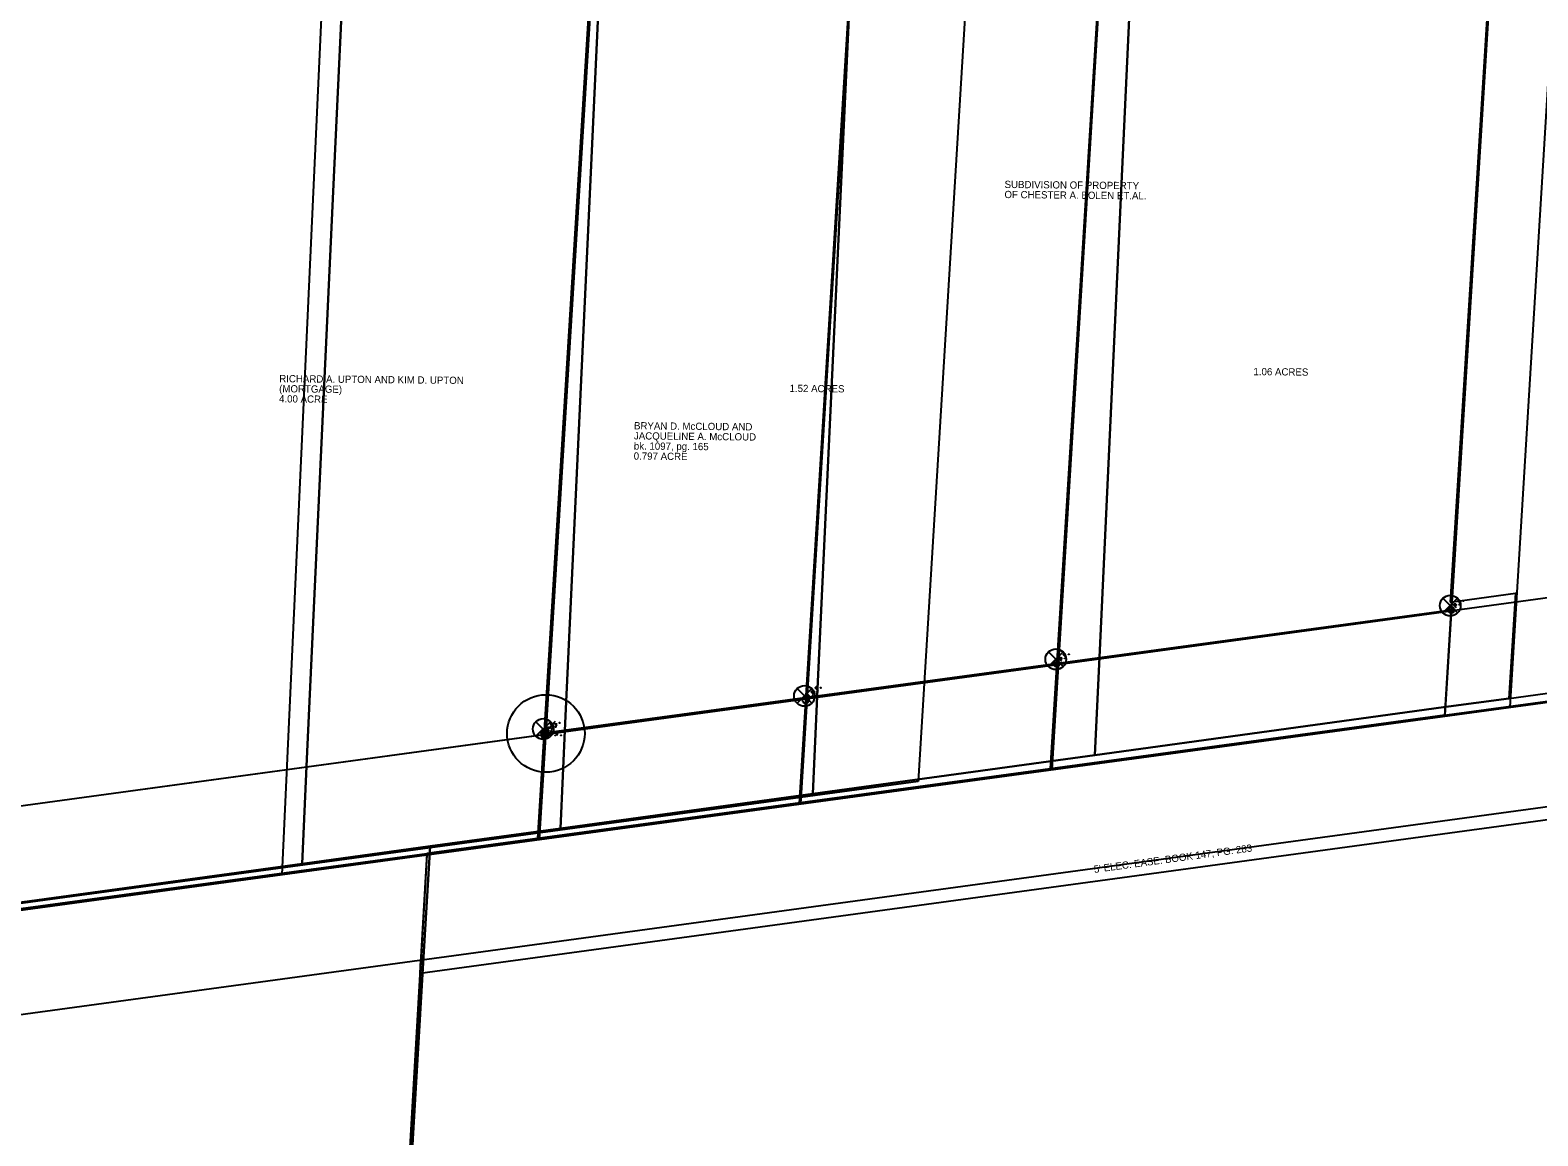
# Model space of a CAD drawing. Extents: x 1532954 to 1577849, y 698998 to 706606.
# Drawn here: x 1572810 to 1573393, y 702918 to 703345 of the extents above; entities that cross this region are included whole.
import ezdxf

# ---------------------------------------------------------------- set-up
doc = ezdxf.new("R2010")
doc.units = 0
for name, color, linetype in [('Default', 7, 'Continuous'), ('DV_X_Lot_Line', 7, 'Continuous'), ('DV_X_Property_Line', 7, 'Continuous'), ('RW_X_CL', 7, 'Continuous'), ('RW_X_Esmt_SH', 7, 'Continuous'), ('RW_X_Esmt_U', 7, 'Continuous'), ('RW_X_Fee_RW', 7, 'Continuous'), ('RW_X_Text', 7, 'Continuous'), ('SC_Scratch1', 7, 'Continuous'), ('SC_Scratch10', 7, 'Continuous'), ('SC_Scratch2', 7, 'Continuous'), ('SC_Scratch3', 7, 'Continuous'), ('SC_Scratch4', 7, 'Continuous'), ('SC_Scratch9', 7, 'Continuous'), ('SV_X_Mon_Cells_Found', 7, 'Continuous')]:
    doc.layers.add(name, color=color, linetype=linetype)

msp = doc.modelspace()

# ---------------------------------------------------------------- linework, layer by layer
at = {"layer": 'Default'}
for p, q in [((1573356.22, 703125.76), (1573361.88, 703120.1)), ((1573356.22, 703120.1), (1573361.88, 703125.76)), ((1573359.05, 703122.93), (1573359.05, 703122.93)), ((1573203.7, 703105.01), (1573209.36, 703099.35)), ((1573203.7, 703099.35), (1573209.36, 703105.01)), ((1573206.53, 703102.18), (1573206.53, 703102.18)), ((1573106.52, 703090.83), (1573112.18, 703085.17)), ((1573106.52, 703085.17), (1573112.18, 703090.83)), ((1573109.35, 703088), (1573109.35, 703088)), ((1573005.53, 703078.04), (1573011.18, 703072.39)), ((1573005.53, 703072.39), (1573011.18, 703078.04)), ((1573008.35, 703075.22), (1573008.35, 703075.22))]:
    msp.add_line(p, q, dxfattribs=at)
for centre in [(1573359.05, 703122.93), (1573206.53, 703102.18), (1573109.35, 703088), (1573008.35, 703075.22)]:
    msp.add_circle(centre, 4, dxfattribs=at)
at = {"layer": 'DV_X_Lot_Line'}
msp.add_line((1572963.4, 703026.58), (1572823.01, 700550.44), dxfattribs=at)
at = {"layer": 'DV_X_Property_Line'}
for p, q in [((1572907.39, 703018.94), (1572924.6, 703393.96)), ((1573006.97, 703032.51), (1573028.82, 703388.75)), ((1573108.02, 703046.29), (1573128.72, 703383.76)), ((1573205.13, 703059.52), (1573224.73, 703378.97))]:
    msp.add_line(p, q, dxfattribs=at)
at = {"layer": 'RW_X_CL'}
msp.add_line((1573382.25, 703083.67), (1573411.32, 703561.68), dxfattribs=at)
at = {"layer": 'RW_X_Esmt_SH'}
for p, q in [((1571959, 702849.32), (1574870.56, 703246.15)), ((1571963.78, 702930.71), (1573359.47, 703120.93))]:
    msp.add_line(p, q, dxfattribs=at)
at = {"layer": 'RW_X_Esmt_U'}
for q in [(1573728.73, 703085.47), (1572961.09, 702985.9)]:
    msp.add_line((1572960.8, 702980.81), q, dxfattribs=at)
at = {"layer": 'RW_X_Fee_RW'}
msp.add_line((1573356.99, 703080.22), (1573386.06, 703558.24), dxfattribs=at)
at = {"layer": 'SC_Scratch1'}
for points in [[(1572932.18, 703390.15), (1572927.2, 703283.07), (1572917, 703063.72), (1572915.11, 703023.08), (1572800.34, 703007.35), (1572687.31, 702991.85), (1572689.2, 703032.48), (1572701.55, 703298.03), (1572706.35, 703401.33), (1572818.4, 703395.78)], [(1573031.18, 703385.25), (1573026.13, 703276.51), (1573016.87, 703077.41), (1573014.98, 703036.77), (1572964.59, 703029.87), (1572915.11, 703023.08), (1572917, 703063.72), (1572927.2, 703283.07), (1572932.18, 703390.15)], [(1573127.9, 703380.47), (1573122.77, 703270.11), (1573114.43, 703090.78), (1573112.54, 703050.15), (1573014.98, 703036.77), (1573016.87, 703077.41), (1573026.13, 703276.51), (1573031.18, 703385.25)], [(1573174.57, 703378.16), (1573225.57, 703375.64), (1573236.04, 703375.12), (1573223.52, 703105.74), (1573221.63, 703065.11), (1573207.45, 703063.17), (1573112.54, 703050.15), (1573114.43, 703090.78), (1573122.77, 703270.11), (1573127.9, 703380.47)], [(1573359.05, 703124.32), (1573384.32, 703127.79), (1573381.77, 703087.06), (1573356.5, 703083.6), (1573221.63, 703065.11), (1573223.52, 703105.74), (1573236.04, 703375.12), (1573374.34, 703368.27)]]:
    msp.add_lwpolyline(points, close=True, dxfattribs=at)
for points in [[(1572818.71, 700543.9), (1572962.2, 702989.16), (1572964.59, 703029.87), (1573014.98, 703036.77), (1573112.54, 703050.15), (1573207.45, 703063.17), (1573221.63, 703065.11), (1573356.5, 703083.6), (1573381.77, 703087.06), (1573407.03, 703090.53)], [(1572365.62, 701708.75), (1572371.48, 701808.58), (1572376.97, 701902.02), (1572377.3, 701908.41), (1572382.44, 702008.28), (1572387.57, 702108.15), (1572392.71, 702208.02), (1572397.85, 702307.89), (1572401.43, 702377.55), (1572403.22, 702407.75), (1572409.15, 702507.57), (1572415.08, 702607.4), (1572380.43, 702909.4), (1572375.87, 702949.15), (1572687.31, 702991.85), (1572800.34, 703007.35), (1572915.11, 703023.08), (1572964.59, 703029.87), (1572962.2, 702989.16), (1572818.71, 700543.9)]]:
    msp.add_lwpolyline(points, dxfattribs=at)
at = {"layer": 'SC_Scratch10'}
for p, q in [((1571190.11, 702825.26), (1574958.12, 703338.82)), ((1571190.11, 702825.26), (1574958.12, 703338.82)), ((1571190.11, 702825.26), (1574958.12, 703338.82)), ((1571195.51, 702785.63), (1574963.52, 703299.19)), ((1571200.91, 702745.99), (1574968.92, 703259.55))]:
    msp.add_line(p, q, dxfattribs=at)
at = {"layer": 'SC_Scratch2'}
for p, q in [((1573356.99, 703080.23), (1573386.06, 703558.24)), ((1573382.25, 703083.67), (1573411.32, 703561.68)), ((1573006.3, 703032.86), (1573028.3, 703388.98)), ((1573128.16, 703383.68), (1573107.32, 703046.43)), ((1574037.66, 703173), (1573356.99, 703080.23)), ((1573356.97, 703080.57), (1573107.32, 703046.6)), ((1573107.32, 703046.6), (1573006.3, 703032.86))]:
    msp.add_line(p, q, dxfattribs=at)
for points in [[(1573110.66, 703088.33), (1573110.92, 703088.58)], [(1573111.91, 703087.31), (1573110.79, 703088.46)], [(1573111.79, 703087.19), (1573112.04, 703087.44)], [(1573113.03, 703088.41), (1573111.91, 703089.55), (1573112.29, 703089.92), (1573112.33, 703089.95), (1573112.41, 703089.99), (1573112.45, 703089.99), (1573112.49, 703090), (1573112.56, 703089.98), (1573112.63, 703089.96), (1573112.72, 703089.91), (1573112.82, 703089.8), (1573112.85, 703089.75), (1573112.89, 703089.68), (1573112.92, 703089.59), (1573112.91, 703089.53), (1573112.91, 703089.49), (1573112.89, 703089.43), (1573112.83, 703089.36), (1573112.46, 703088.99)], [(1573112.45, 703088.14), (1573112.49, 703088.18), (1573112.53, 703088.18), (1573112.59, 703088.17), (1573112.63, 703088.12), (1573112.64, 703088.06), (1573112.64, 703088.02), (1573112.6, 703087.98), (1573112.55, 703087.98), (1573112.5, 703087.99), (1573112.45, 703088.04), (1573112.44, 703088.1), (1573112.45, 703088.14)], [(1573114.06, 703091.66), (1573113.51, 703091.13), (1573114.63, 703089.98)], [(1573114.05, 703089.71), (1573114.09, 703089.75), (1573114.13, 703089.76), (1573114.19, 703089.74), (1573114.23, 703089.7), (1573114.25, 703089.64), (1573114.24, 703089.6), (1573114.2, 703089.56), (1573114.16, 703089.55), (1573114.1, 703089.57), (1573114.06, 703089.61), (1573114.05, 703089.67), (1573114.05, 703089.71)], [(1573114.06, 703090.57), (1573114.45, 703090.95)], [(1573115.59, 703091.22), (1573115.62, 703091.26), (1573115.67, 703091.26), (1573115.73, 703091.25), (1573115.77, 703091.2), (1573115.78, 703091.14), (1573115.77, 703091.1), (1573115.74, 703091.06), (1573115.69, 703091.06), (1573115.64, 703091.07), (1573115.59, 703091.12), (1573115.58, 703091.18), (1573115.59, 703091.22)], [(1573009.64, 703074.76), (1573009.89, 703075.01)], [(1573010.89, 703073.74), (1573009.77, 703074.89)], [(1573012, 703074.84), (1573010.88, 703075.98), (1573011.26, 703076.35), (1573011.31, 703076.38), (1573011.38, 703076.42), (1573011.42, 703076.42), (1573011.46, 703076.43), (1573011.54, 703076.41), (1573011.61, 703076.39), (1573011.69, 703076.34), (1573011.8, 703076.23), (1573011.83, 703076.18), (1573011.86, 703076.11), (1573011.89, 703076.02), (1573011.89, 703075.96), (1573011.88, 703075.92), (1573011.86, 703075.87), (1573011.81, 703075.79), (1573011.43, 703075.42)], [(1573011.42, 703074.57), (1573011.46, 703074.61), (1573011.5, 703074.61), (1573011.56, 703074.6), (1573011.6, 703074.55), (1573011.62, 703074.49), (1573011.61, 703074.45), (1573011.57, 703074.42), (1573011.53, 703074.41), (1573011.47, 703074.42), (1573011.43, 703074.47), (1573011.41, 703074.53), (1573011.42, 703074.57)], [(1573013.03, 703078.09), (1573012.49, 703077.56), (1573013.61, 703076.41)], [(1573013.03, 703076.14), (1573013.07, 703076.18), (1573013.11, 703076.19), (1573013.17, 703076.17), (1573013.21, 703076.13), (1573013.22, 703076.07), (1573013.22, 703076.03), (1573013.18, 703075.99), (1573013.13, 703075.98), (1573013.08, 703076), (1573013.03, 703076.04), (1573013.02, 703076.1), (1573013.03, 703076.14)], [(1573013.04, 703077), (1573013.42, 703077.38)], [(1573014.56, 703077.65), (1573014.6, 703077.69), (1573014.64, 703077.69), (1573014.7, 703077.68), (1573014.74, 703077.63), (1573014.76, 703077.57), (1573014.75, 703077.53), (1573014.71, 703077.49), (1573014.67, 703077.49), (1573014.61, 703077.5), (1573014.57, 703077.55), (1573014.55, 703077.61), (1573014.56, 703077.65)], [(1573010.76, 703073.62), (1573011.01, 703073.87)]]:
    msp.add_lwpolyline(points, dxfattribs=at)
for centre in [(1573109.79, 703086.35), (1573008.76, 703072.78)]:
    msp.add_circle(centre, 1.2, dxfattribs=at)
at = {"layer": 'SC_Scratch3'}
for p, q in [((1573173.45, 703383.28), (1573153.38, 703054.89)), ((1574533, 703240.3), (1572963.42, 703027.05)), ((1573153.38, 703054.89), (1572680.88, 702990.69)), ((1572963.42, 703027.05), (1572822.18, 700549.47))]:
    msp.add_line(p, q, dxfattribs=at)
at = {"layer": 'SC_Scratch4'}
for p, q in [((1573006.23, 703032.86), (1573028.3, 703388.98)), ((1573224.15, 703378.38), (1573204.41, 703059.79)), ((1573374.95, 703371.15), (1573356.94, 703080.51)), ((1573359.46, 703121.22), (1573008.75, 703073.57)), ((1573356.94, 703080.51), (1573204.41, 703059.79)), ((1573204.41, 703059.79), (1573006.23, 703032.86)), ((1572041.35, 702901.76), (1573006.23, 703032.86)), ((1572963.42, 703027), (1572375.91, 702947.21)), ((1572963.42, 703027), (1572817.89, 700552.97))]:
    msp.add_line(p, q, dxfattribs=at)
for points in [[(1573361.44, 703122.05), (1573360.32, 703123.19), (1573360.7, 703123.56), (1573360.75, 703123.59), (1573360.82, 703123.63), (1573360.86, 703123.63), (1573360.91, 703123.64), (1573360.98, 703123.62), (1573361.05, 703123.6), (1573361.14, 703123.55), (1573361.24, 703123.44), (1573361.27, 703123.39), (1573361.31, 703123.32), (1573361.34, 703123.23), (1573361.33, 703123.17), (1573361.33, 703123.13), (1573361.3, 703123.08), (1573361.25, 703123), (1573360.87, 703122.63)], [(1573362.47, 703125.3), (1573361.93, 703124.77), (1573363.05, 703123.62)], [(1573362.47, 703123.35), (1573362.51, 703123.39), (1573362.55, 703123.4), (1573362.61, 703123.38), (1573362.65, 703123.34), (1573362.66, 703123.28), (1573362.66, 703123.24), (1573362.62, 703123.2), (1573362.58, 703123.19), (1573362.52, 703123.21), (1573362.47, 703123.25), (1573362.46, 703123.31), (1573362.47, 703123.35)], [(1573362.48, 703124.21), (1573362.86, 703124.59)], [(1573364, 703124.86), (1573364.04, 703124.9), (1573364.08, 703124.9), (1573364.14, 703124.89), (1573364.19, 703124.84), (1573364.2, 703124.78), (1573364.19, 703124.74), (1573364.15, 703124.7), (1573364.11, 703124.7), (1573364.05, 703124.71), (1573364.01, 703124.76), (1573364, 703124.82), (1573364, 703124.86)], [(1573209.94, 703104.57), (1573209.4, 703104.04), (1573210.52, 703102.9)], [(1573209.95, 703103.48), (1573210.33, 703103.86)], [(1573211.47, 703104.13), (1573211.51, 703104.17), (1573211.55, 703104.18), (1573211.61, 703104.16), (1573211.66, 703104.12), (1573211.67, 703104.06), (1573211.66, 703104.02), (1573211.62, 703103.98), (1573211.58, 703103.97), (1573211.52, 703103.99), (1573211.48, 703104.03), (1573211.47, 703104.09), (1573211.47, 703104.13)], [(1573208.92, 703101.33), (1573207.8, 703102.47), (1573208.17, 703102.84), (1573208.22, 703102.87), (1573208.29, 703102.9), (1573208.34, 703102.91), (1573208.38, 703102.91), (1573208.45, 703102.9), (1573208.52, 703102.88), (1573208.61, 703102.82), (1573208.71, 703102.71), (1573208.74, 703102.67), (1573208.78, 703102.6), (1573208.81, 703102.51), (1573208.8, 703102.45), (1573208.8, 703102.41), (1573208.77, 703102.35), (1573208.72, 703102.28), (1573208.34, 703101.91)], [(1573209.94, 703102.63), (1573209.98, 703102.67), (1573210.02, 703102.67), (1573210.08, 703102.66), (1573210.12, 703102.61), (1573210.13, 703102.55), (1573210.13, 703102.51), (1573210.09, 703102.48), (1573210.05, 703102.47), (1573209.99, 703102.48), (1573209.94, 703102.53), (1573209.93, 703102.59), (1573209.94, 703102.63)], [(1573010.74, 703074.4), (1573009.62, 703075.54), (1573009.99, 703075.91), (1573010.04, 703075.94), (1573010.12, 703075.98), (1573010.16, 703075.98), (1573010.2, 703075.99), (1573010.27, 703075.97), (1573010.34, 703075.95), (1573010.43, 703075.89), (1573010.53, 703075.79), (1573010.56, 703075.74), (1573010.6, 703075.67), (1573010.63, 703075.58), (1573010.62, 703075.52), (1573010.62, 703075.48), (1573010.6, 703075.42), (1573010.54, 703075.35), (1573010.16, 703074.98)], [(1573011.77, 703077.65), (1573011.22, 703077.11), (1573012.34, 703075.97)], [(1573011.76, 703075.7), (1573011.8, 703075.74), (1573011.84, 703075.74), (1573011.9, 703075.73), (1573011.94, 703075.69), (1573011.96, 703075.63), (1573011.95, 703075.59), (1573011.91, 703075.55), (1573011.87, 703075.54), (1573011.81, 703075.56), (1573011.77, 703075.6), (1573011.75, 703075.66), (1573011.76, 703075.7)], [(1573011.77, 703076.56), (1573012.16, 703076.94)], [(1573013.29, 703077.21), (1573013.33, 703077.24), (1573013.38, 703077.25), (1573013.43, 703077.24), (1573013.48, 703077.19), (1573013.49, 703077.13), (1573013.48, 703077.09), (1573013.44, 703077.05), (1573013.4, 703077.05), (1573013.34, 703077.06), (1573013.3, 703077.11), (1573013.29, 703077.16), (1573013.29, 703077.21)]]:
    msp.add_lwpolyline(points, dxfattribs=at)
for centre, radius in [((1573359.46, 703121.22), 1.2), ((1573359.46, 703121.22), 0.495), ((1573206.93, 703100.5), 1.2), ((1573206.93, 703100.5), 0.495), ((1573008.75, 703073.57), 1.2), ((1573008.75, 703073.57), 0.495)]:
    msp.add_circle(centre, radius, dxfattribs=at)
at = {"layer": 'SC_Scratch9'}
msp.add_circle((1573009.4, 703073.48), 15, dxfattribs=at)
at = {"layer": 'SV_X_Mon_Cells_Found'}
for points in [[(1573011.39, 703072.68), (1573011.39, 703074.28), (1573011.92, 703074.28), (1573011.98, 703074.26), (1573012.05, 703074.24), (1573012.09, 703074.21), (1573012.12, 703074.19), (1573012.16, 703074.12), (1573012.2, 703074.06), (1573012.22, 703073.96), (1573012.22, 703073.81), (1573012.21, 703073.76), (1573012.19, 703073.68), (1573012.14, 703073.6), (1573012.1, 703073.56), (1573012.06, 703073.53), (1573012.01, 703073.51), (1573011.92, 703073.49), (1573011.39, 703073.49)], [(1573014.4, 703074.28), (1573013.64, 703074.28), (1573013.64, 703072.68)], [(1573013.03, 703072.89), (1573013.09, 703072.89), (1573013.12, 703072.86), (1573013.16, 703072.81), (1573013.16, 703072.75), (1573013.12, 703072.7), (1573013.09, 703072.68), (1573013.03, 703072.68), (1573013, 703072.7), (1573012.97, 703072.75), (1573012.97, 703072.81), (1573013, 703072.86), (1573013.03, 703072.89)], [(1573013.64, 703073.49), (1573014.18, 703073.49)], [(1573015.18, 703072.89), (1573015.24, 703072.89), (1573015.27, 703072.86), (1573015.31, 703072.81), (1573015.31, 703072.75), (1573015.27, 703072.7), (1573015.24, 703072.68), (1573015.18, 703072.68), (1573015.15, 703072.7), (1573015.12, 703072.75), (1573015.12, 703072.81), (1573015.15, 703072.86), (1573015.18, 703072.89)]]:
    msp.add_lwpolyline(points, dxfattribs=at)
for radius in [1.2, 0.495]:
    msp.add_circle((1573009.4, 703073.48), radius, dxfattribs=at)

# ---------------------------------------------------------------- texts
at = {"layer": 'RW_X_Text'}
msp.add_text("5' ELEC. EASE. BOOK 147, PG. 283", height=2.8, rotation=7.76869, dxfattribs=at).set_placement((1573221.44, 703019.55))
at = {"layer": 'SC_Scratch2'}
for s, p in [('BRYAN D. McCLOUD AND', (1573043.45, 703191.1)), ('JACQUELINE A. McCLOUD', (1573043.42, 703187.2)), ('bk. 1097, pg. 165', (1573043.38, 703183.29)), ('0.797 ACRE', (1573043.34, 703179.39))]:
    msp.add_text(s, height=2.8, rotation=359.44829, dxfattribs=at).set_placement(p)
at = {"layer": 'SC_Scratch3'}
for s, p in [('(MORTGAGE)', (1572906.24, 703205.42)), ('RICHARD A. UPTON AND KIM D. UPTON', (1572906.28, 703209.32)), ('4.00 ACRE', (1572906.21, 703201.52))]:
    msp.add_text(s, height=2.8, rotation=359.43722, dxfattribs=at).set_placement(p)
at = {"layer": 'SC_Scratch4'}
for s, p in [('SUBDIVISION OF PROPERTY', (1573186.72, 703284.42)), ('OF CHESTER A. BOLEN ET.AL.', (1573186.68, 703280.52)), ('1.06 ACRES', (1573282.95, 703212.04)), ('1.52 ACRES', (1573103.59, 703205.56))]:
    msp.add_text(s, height=2.8, rotation=359.43748, dxfattribs=at).set_placement(p)

doc.saveas('drawing.dxf')
